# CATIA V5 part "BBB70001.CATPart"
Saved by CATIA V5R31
Part number: BBB70001
Revision: 1
Nomenclature: BRKT_A
Source: Unknown
Property "部品番号(A社)": "BBB70001"
Property "部品名称(A社)": "BRKT_A"
Property "Version(A社)": "1"
Property "材質": "JSH270C"
Property "板厚": "4.5"
Bounding box of the stored display mesh (mm): x -731.538 to -635.7, y -69.901 to 4.599, z -55.354 to 46.583
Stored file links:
  \\cad-nas02\CATIA1212\BODY_DEPARTMENT8\JAMA\変換データ\STEP3_最終_20240115\01_いすゞ板金\new_ファイル名修正後\CATIA_V5_20240122\BBB70001.CATPart
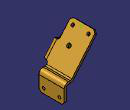
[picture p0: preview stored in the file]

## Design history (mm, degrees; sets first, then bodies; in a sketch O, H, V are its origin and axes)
Set1
  DatumPoint1
Body1 "MANIFOLD_SOLID_BREP #330" (main body)
  Solid1: solid without history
